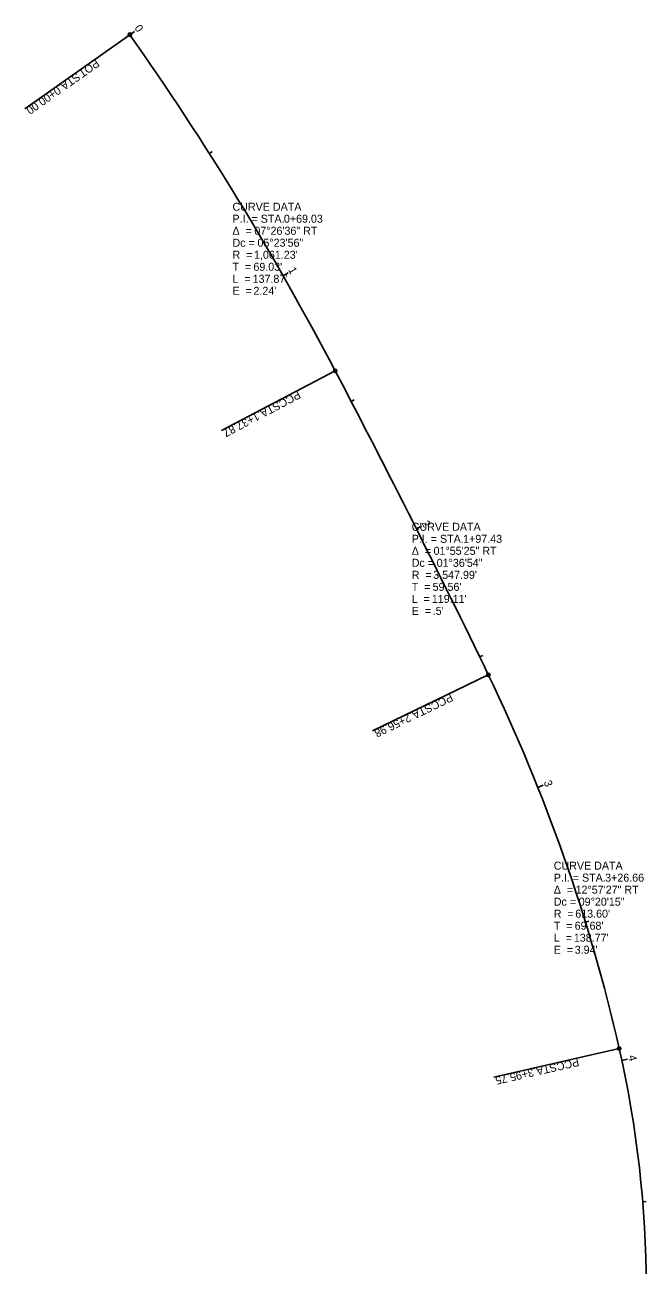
# Model space of a CAD drawing. Extents: x 2376685 to 2376908, y 700340 to 701208.
# Drawn here: x 2376685.4 to 2376903, y 700774.3 to 701208.1 of the extents above; entities that cross this region are included whole.
import ezdxf

# ---------------------------------------------------------------- set-up
doc = ezdxf.new("R2010")
doc.units = 0
for name, color, linetype in [('Default', 7, 'Continuous'), ('GE_X_Alignment', 7, 'Continuous'), ('GE_X_Alignment_100_Cardinal_Points', 7, 'Continuous'), ('GE_X_Alignment_100_Curve_Data', 7, 'Continuous'), ('GE_X_Alignment_100_Stations', 7, 'Continuous')]:
    doc.layers.add(name, color=color, linetype=linetype)

msp = doc.modelspace()

# ---------------------------------------------------------------- linework, layer by layer
at = {"layer": 'Default'}
for centre, radius, start, end in [((2373653.32, 699436.65), 3547.99, 25.79802, 27.72153), ((2376295.25, 700713.69), 613.6, 12.84046, 25.79802), ((2376524.38, 700765.92), 378.59, 322.1906, 12.8405)]:
    msp.add_arc(centre, radius, start, end, dxfattribs=at)
at = {"layer": 'GE_X_Alignment'}
for centre, radius, start, end in [((2375854.64, 700593.42), 1061.23, 27.72153, 35.16498), ((2373653.32, 699436.65), 3547.99, 25.79802, 27.72153), ((2376295.25, 700713.69), 613.6, 12.84046, 25.79802), ((2376524.38, 700765.92), 378.59, 322.1906, 12.8405)]:
    msp.add_arc(centre, radius, start, end, dxfattribs=at)
at = {"layer": 'GE_X_Alignment_100_Cardinal_Points'}
for p, q in [((2376722.2, 701204.62), (2376685.41, 701178.71)), ((2376794.06, 701087.08), (2376754.23, 701066.15)), ((2376847.69, 700980.73), (2376807.18, 700961.15)), ((2376893.5, 700850.06), (2376849.63, 700840.06))]:
    msp.add_line(p, q, dxfattribs=at)
for centre in [(2376722.2, 701204.62), (2376794.06, 701087.08), (2376847.69, 700980.73), (2376893.5, 700850.06)]:
    msp.add_circle(centre, 0.6, dxfattribs=at)
at = {"layer": 'GE_X_Alignment_100_Stations'}
for p, q in [((2376722.2, 701204.62), (2376723.83, 701205.77)), ((2376750.02, 701163.08), (2376751.03, 701163.73)), ((2376775.86, 701120.28), (2376777.59, 701121.28)), ((2376799.69, 701076.33), (2376800.75, 701076.89)), ((2376822.48, 701031.83), (2376824.27, 701032.73)), ((2376844.65, 700987.01), (2376845.73, 700987.54)), ((2376865.04, 700941.37), (2376866.9, 700942.12)), ((2376881.68, 700894.24), (2376882.83, 700894.59)), ((2376894.43, 700845.91), (2376896.38, 700846.33)), ((2376901.74, 700796.48), (2376902.93, 700796.58))]:
    msp.add_line(p, q, dxfattribs=at)

# ---------------------------------------------------------------- texts
at = {"layer": 'GE_X_Alignment_100_Cardinal_Points'}
for s, rotation, p in [('POT', 215.165, (2376710.25, 701196.16)), (' STA. ', 215.165, (2376704.43, 701192.06)), ('0+00.00', 215.165, (2376696.8, 701186.69)), ('PCC', 207.7215, (2376781.03, 701080.19)), (' STA. ', 207.7215, (2376774.87, 701076.95)), ('1+37.87', 207.7215, (2376766.62, 701072.62)), ('PCC', 205.798, (2376834.44, 700974.29)), (' STA. ', 205.798, (2376828.17, 700971.26)), ('2+56.98', 205.798, (2376819.78, 700967.2)), (' STA. ', 192.8405, (2376872.32, 700845.19)), ('PCC', 192.8405, (2376879.1, 700846.74)), ('3+95.75', 192.8405, (2376863.23, 700843.12))]:
    msp.add_text(s, height=2.8, rotation=rotation, dxfattribs=at).set_placement(p)
at = {"layer": 'GE_X_Alignment_100_Curve_Data'}
for s, p in [('CURVE DATA', (2376758.13, 701143.05)), ('P.I. = STA. ', (2376758.13, 701138.85)), ('0+69.03', (2376776.12, 701138.85)), ('Δ  = ', (2376758.13, 701134.65)), ('07°26\'36" RT', (2376765.78, 701134.65)), ('Dc = ', (2376758.13, 701130.45)), ('05°23\'56"', (2376766.87, 701130.45)), ('R  = ', (2376758.13, 701126.25)), ("1,061.23'", (2376765.67, 701126.25)), ('T  = ', (2376758.13, 701122.05)), ("69.03'", (2376765.45, 701122.05)), ('L  = ', (2376758.13, 701117.85)), ('E  = ', (2376758.13, 701113.65)), ("137.87'", (2376765.17, 701117.85)), ("2.24'", (2376765.47, 701113.65)), ('CURVE DATA', (2376820.88, 701031.11)), ('P.I. = STA. ', (2376820.88, 701026.91)), ('1+97.43', (2376838.87, 701026.91)), ('Δ  = ', (2376820.88, 701022.71)), ('01°55\'25" RT', (2376828.52, 701022.71)), ('Dc = ', (2376820.88, 701018.51)), ('01°36\'54"', (2376829.62, 701018.51)), ('R  = ', (2376820.88, 701014.31)), ("3,547.99'", (2376828.41, 701014.31)), ('T  = ', (2376820.88, 701010.11)), ("59.56'", (2376828.2, 701010.11)), ('L  = ', (2376820.88, 701005.91)), ("119.11'", (2376827.91, 701005.91)), ('E  = ', (2376820.88, 701001.71)), (".5'", (2376828.22, 701001.71)), ('CURVE DATA', (2376870.6, 700912.6)), ('P.I. = STA. ', (2376870.6, 700908.4)), ('3+26.66', (2376888.59, 700908.4)), ('Δ  = ', (2376870.6, 700904.2)), ('12°57\'27" RT', (2376878.24, 700904.2)), ('Dc = ', (2376870.6, 700900)), ('09°20\'15"', (2376879.34, 700900)), ('R  = ', (2376870.6, 700895.8)), ("613.60'", (2376878.13, 700895.8)), ('T  = ', (2376870.6, 700891.6)), ("69.68'", (2376877.92, 700891.6)), ('L  = ', (2376870.6, 700887.4)), ("138.77'", (2376877.63, 700887.4)), ('E  = ', (2376870.6, 700883.2)), ("3.94'", (2376877.94, 700883.2))]:
    msp.add_text(s, height=2.8, dxfattribs=at).set_placement(p)
at = {"layer": 'GE_X_Alignment_100_Stations'}
for s, rotation, p in [('0', 305.165, (2376723.64, 701206.91)), ('1', 299.766, (2376777.53, 701122.38)), ('2', 296.7182, (2376824.28, 701033.83)), ('3', 291.7809, (2376867.01, 700943.2)), ('4', 282.1967, (2376896.65, 700847.46))]:
    msp.add_text(s, height=2.8, rotation=rotation, dxfattribs=at).set_placement(p)

doc.saveas('drawing.dxf')
